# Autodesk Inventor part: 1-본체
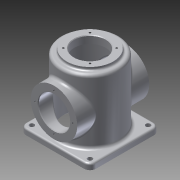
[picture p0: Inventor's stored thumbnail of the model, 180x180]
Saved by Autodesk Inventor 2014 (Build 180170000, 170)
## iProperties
Created: 2015-10
Part Number: 1-본체
Material: 알루미늄 6061
Document SubType Name: Modeling
Designer: SEC
Density: 2.71 g/cm^3
Appearance: 알루미늄 - 평지
Mass: 919.32 g
Surface Area: 1017.67 cm^2
Volume: 339.233 cm^3
Author: SEC
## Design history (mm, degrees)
sketch "스케치1"
  geometry: C1 r 50 at (0, 0); 1 further point
  constraints: 1 centre point, 1 coincident
  dimensions: "d0" = 100 diameter of C1
extrude "돌출1" new body sketch "스케치1" distance "d1" = 60; taper "d2" = 0 deg; dims "d85" = 55, "d86" = 0
node "작업 평면1"
sketch "스케치2"
  geometry: L1 (-60, 60)-(60, 60); L2 (60, 60)-(60, -60); L3 (60, -60)-(-60, -60); L4 (-60, -60)-(-60, 60); 1 further point
  constraints: 8 end point, 2 parallel, 1 horizontal, 1 perpendicular
  dimensions: "d4" = 120 distance of L1.start L1.end; "d5" = 120 distance of L1.end L2.end; "d6" = 60 distance from line of L1 point (0, 0); "d7" = 60 distance from line of L4 point (0, 0)
extrude "돌출2" join sketch "스케치2" distance "d8" = 10; taper "d9" = 0 deg
sketch "스케치3"
  geometry: C1 r 50 at (0, 0) reference; C2 r 40 at (0, 0)
  constraints: 1 centre point, 1 coincident
  dimensions: "d10" = 80 diameter of C2
extrude "돌출3" join sketch "스케치3" distance "d11" = 5; taper "d12" = 0 deg
hole "구멍1" diameter "d15" = 54; stored, may be unused: countersink angle "d19" = 90 deg, drill point angle "d21" = 118 deg; dims "d13" = 10, "d14" = 10, "d16" = 6, "d17" = 4, "d18" = 2, "d20" = 8
sketch "스케치4"
  geometry: C1 r 27 at (0, 0) reference; C2 r 45 at (0, 0)
  constraints: 1 centre point, 1 coincident
  dimensions: "d22" = 90 diameter of C2
extrude "돌출4" cut sketch "스케치4" distance "d23" = 112; taper "d24" = 0 deg
node "작업 평면2"
sketch "스케치5"
  geometry: C1 r 40 at (0, 0); 1 further point
  constraints: 1 centre point, 1 coincident
  dimensions: "d26" = 80 diameter of C1
extrude "돌출5" join sketch "스케치5" stored distance "d27" = 112; taper "d28" = 0 deg
hole "구멍2" diameter "d31" = 54; stored, may be unused: countersink angle "d35" = 90 deg, drill point angle "d37" = 118 deg; dims "d29" = 10, "d30" = 10, "d32" = 6, "d33" = 4, "d34" = 2, "d36" = 8
hole "구멍3" diameter "d40" = 8; stored, may be unused: countersink angle "d44" = 90 deg, drill point angle "d46" = 118 deg; dims "d38" = 10, "d39" = 10, "d41" = 6, "d42" = 4, "d43" = 2, "d45" = 8
sketch "스케치6"
  geometry: C1 r 27 at (0, 0) reference; 1 further point
  constraints: 1 vertical alignment
  dimensions: "d47" = 32.5 distance of C1.centre point (0, 32.5)
hole "구멍4" sketch "스케치6" at (0, 32.5) diameter "d48" = 3.242; stored, may be unused: countersink angle "d52" = 90 deg, drill point angle "d54" = 118 deg; dims "d49" = 8, "d50" = 4, "d51" = 2, "d53" = 10
sketch "스케치7"
  geometry: L1 (0, 0)-(32.5, 0); L2 (0, 0)-(22.981, 22.981); C1 r 40 at (0, 0) reference; A1 r 32.5 centre (0, 0) between (32.5, 0) and (22.981, 22.981); 1 further point
  constraints: 4 end point, 2 coincident, 2 point on circle, 1 centre point, 1 horizontal
  dimensions: "d58" = 65 diameter of A1; "d59" = 45 deg angle of L1 L2
hole "구멍5" sketch "스케치7" at (22.981, 22.981) diameter "d60" = 3.242; stored, may be unused: countersink angle "d64" = 90 deg, drill point angle "d66" = 118 deg; dims "d61" = 8, "d62" = 4, "d63" = 2, "d65" = 10
chamfer "모따기1" distance "d70" = 1; stored, may be unused: second distance "d71" = 2, angle "d72" = 45 deg
chamfer "모따기2" distance "d73" = 3; stored, may be unused: second distance "d74" = 2, angle "d75" = 45 deg
fillet "모깎기1" dims "d76" = 5
fillet "모깎기2" dims "d77" = 10
fillet "모깎기3" dims "d78" = 3
fillet "모깎기4" dims "d79" = 3
fillet "모깎기5" dims "d80" = 5
node "작업 평면3"
sketch "스케치8"
  geometry: L1 (60, 50)-(60, -50) reference; 2 further points
  constraints: 1 horizontal alignment, 1 midpoint, 1 other
  dimensions: "d90" = 70 distance from line of point (-10, 0) L1
feature "엠보싱1" sketch "스케치8" dims "d2" = 0, "d82" = 0.5, "d83" = 0
fillet "모깎기6" dims "d84" = 3
chamfer "모따기3" distance "d87" = 1; stored, may be unused: second distance "d88" = 2, angle "d89" = 45 deg
node "솔리드1"
mirror "대칭1"
mirror "대칭2"
mirror "대칭3"
mirror "대칭4"
pattern_circular "원형 패턴1" dims angle "d56" = 360 deg
pattern_circular "원형 패턴2" dims angle "d68" = 360 deg
other parameters: "d25" = 62
